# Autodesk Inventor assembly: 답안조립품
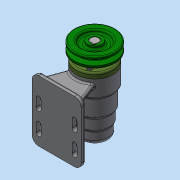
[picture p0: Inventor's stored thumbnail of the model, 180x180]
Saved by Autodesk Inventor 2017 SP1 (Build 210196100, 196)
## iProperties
Part Number: 답안조립품
Material: 일반
Document SubType Name: Assembly
Designer: MRC
Author: MRC
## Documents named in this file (12)
- C:\Users\MRC\Desktop\711009V1002\답안조립품.iam
- C:\Users\MRC\Desktop\711009V1002\본체.ipt
- C:\Users\MRC\Desktop\711009V1002\V벨트풀리.ipt
- C:\Users\MRC\Desktop\711009V1002\멈춤나사 M3.ipt
- C:\Users\MRC\Desktop\711009V1002\베어링 6004.ipt
- C:\Users\MRC\Desktop\711009V1002\베어링 51202.ipt
- C:\Users\MRC\Desktop\711009V1002\볼트 M4.ipt
- C:\Users\MRC\Desktop\711009V1002\어댑터슬리브.ipt
- C:\Users\MRC\Desktop\711009V1002\오일 실 20x35x7.ipt
- C:\Users\MRC\Desktop\711009V1002\축.ipt
- C:\Users\MRC\Desktop\711009V1002\커버.ipt
- C:\Users\MRC\Desktop\711009V1002\키 5x5.ipt
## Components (1 placed, 1 different names)
1. V벨트풀리:1 — 플러쉬:1
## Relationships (1: Flush 1)
- 플러쉬:1 [Flush]: V벨트풀리:1
